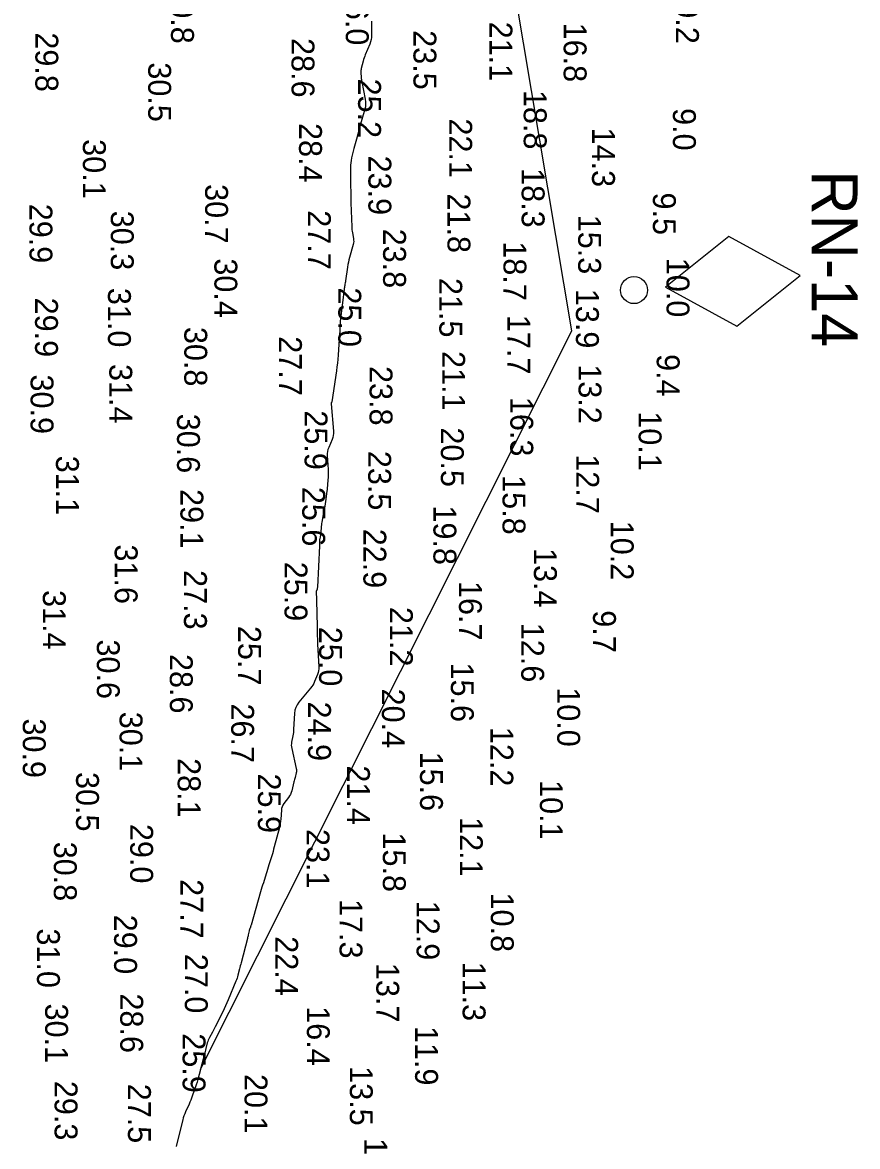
# Model space of a CAD drawing. Extents: x 1178573 to 1187098, y 693282 to 751751.
# Drawn here: x 1180607 to 1181063, y 712737 to 713352 of the extents above; entities that cross this region are included whole.
import ezdxf

# ---------------------------------------------------------------- set-up
doc = ezdxf.new("R2010")
doc.units = 0
for name, color, linetype in [('G-ANNO-PATT', 7, 'Continuous'), ('V-CHAN-NAID', 7, 'Continuous'), ('V-HYDS-MAJR', 7, 'Continuous'), ('V-HYDS-SOUN', 7, 'Continuous'), ('V-HYDS-SOUN-EXSS', 7, 'Continuous')]:
    doc.layers.add(name, color=color, linetype=linetype)

msp = doc.modelspace()

# ---------------------------------------------------------------- linework, layer by layer
at = {"layer": 'G-ANNO-PATT'}
msp.add_line((1180704.33, 712779.5), (1180907.13, 713183.08), dxfattribs=at)
for points in [[(1180907.13, 713183.08), (1180828.13, 713654.46), (1180762.78, 713744.18)], [(1180797.74, 713352.4), (1180797.72, 713351.58), (1180797.71, 713350.75), (1180797.7, 713344.77), (1180797.64, 713343.51), (1180797.46, 713342.28), (1180797.15, 713341.07), (1180796.73, 713339.88), (1180794.29, 713333.99), (1180793.96, 713333.15), (1180793.66, 713332.31), (1180793.39, 713331.45), (1180793.14, 713330.58), (1180792.08, 713326.51), (1180791.95, 713325.92), (1180791.88, 713325.32), (1180791.85, 713324.72), (1180791.87, 713324.12), (1180792.07, 713321.69), (1180792.12, 713321.09), (1180792.2, 713320.48), (1180792.29, 713319.88), (1180792.4, 713319.29), (1180794.25, 713309.72), (1180794.44, 713308.33), (1180794.47, 713306.94), (1180794.33, 713305.56), (1180794.02, 713304.19), (1180792.45, 713298.65), (1180792.08, 713297.31), (1180791.7, 713295.98), (1180791.33, 713294.64), (1180790.95, 713293.31), (1180789.43, 713287.85), (1180789.08, 713286.57), (1180788.74, 713285.29), (1180788.41, 713284.01), (1180788.09, 713282.72), (1180786.83, 713277.58), (1180786.55, 713276.29), (1180786.36, 713274.99), (1180786.25, 713273.68), (1180786.22, 713272.36), (1180786.29, 713261.84), (1180786.31, 713259.64), (1180786.35, 713257.45), (1180786.4, 713255.25), (1180786.46, 713253.06), (1180786.88, 713239.95), (1180786.92, 713239.13), (1180786.99, 713238.32), (1180787.09, 713237.52), (1180787.23, 713236.72), (1180787.83, 713233.51), (1180787.93, 713232.72), (1180787.95, 713231.92), (1180787.87, 713231.13), (1180787.69, 713230.34), (1180785.73, 713223.26), (1180785.39, 713221.95), (1180785.1, 713220.64), (1180784.84, 713219.31), (1180784.63, 713217.98), (1180783.56, 713210.46), (1180783.52, 713210.21), (1180783.48, 713209.96), (1180783.43, 713209.72), (1180783.38, 713209.47), (1180783.17, 713208.48), (1180783.12, 713208.25), (1180783.08, 713208.01), (1180783.04, 713207.77), (1180783, 713207.54), (1180782.87, 713206.59), (1180782.84, 713206.35), (1180782.8, 713206.11), (1180782.77, 713205.87), (1180782.74, 713205.63), (1180780.64, 713188.46), (1180780.58, 713187.89), (1180780.53, 713187.32), (1180780.49, 713186.75), (1180780.46, 713186.18), (1180780.38, 713183.89), (1180780.36, 713183.32), (1180780.33, 713182.75), (1180780.3, 713182.18), (1180780.26, 713181.6), (1180779.46, 713169.8), (1180779.29, 713167.65), (1180779.07, 713165.5), (1180778.82, 713163.35), (1180778.52, 713161.21), (1180775.98, 713144.23), (1180775.97, 713144.16), (1180775.95, 713144.1), (1180775.92, 713144.03), (1180775.88, 713143.97), (1180775.7, 713143.67), (1180775.68, 713143.63), (1180775.67, 713143.59), (1180775.67, 713143.55), (1180775.67, 713143.51), (1180775.7, 713143.34), (1180775.71, 713143.3), (1180775.71, 713143.26), (1180775.72, 713143.21), (1180775.72, 713143.17), (1180776.9, 713128.24), (1180776.93, 713127.08), (1180776.81, 713125.94), (1180776.56, 713124.83), (1180776.16, 713123.74), (1180774.31, 713119.42), (1180773.91, 713118.32), (1180773.65, 713117.21), (1180773.52, 713116.07), (1180773.52, 713114.91), (1180773.97, 713107.29), (1180774.01, 713106.3), (1180774.02, 713105.31), (1180774, 713104.32), (1180773.95, 713103.33), (1180773.68, 713099.37), (1180773.6, 713098.38), (1180773.51, 713097.4), (1180773.4, 713096.41), (1180773.27, 713095.43), (1180772.51, 713089.87), (1180772.33, 713088.62), (1180772.14, 713087.37), (1180771.93, 713086.12), (1180771.71, 713084.88), (1180770.53, 713078.47), (1180770.4, 713077.73), (1180770.29, 713076.99), (1180770.2, 713076.24), (1180770.13, 713075.49), (1180769.8, 713071.54), (1180769.77, 713071.26), (1180769.74, 713070.99), (1180769.69, 713070.72), (1180769.64, 713070.45), (1180769.41, 713069.38), (1180769.36, 713069.12), (1180769.33, 713068.85), (1180769.31, 713068.57), (1180769.3, 713068.3), (1180769.31, 713066.94), (1180769.31, 713066.62), (1180769.31, 713066.3), (1180769.3, 713065.98), (1180769.29, 713065.67), (1180768.13, 713043.08), (1180768.1, 713042.76), (1180768.06, 713042.45), (1180767.99, 713042.14), (1180767.91, 713041.83), (1180767.54, 713040.61), (1180767.47, 713040.3), (1180767.42, 713039.99), (1180767.4, 713039.68), (1180767.42, 713039.36), (1180767.58, 713037.43), (1180767.62, 713037.01), (1180767.65, 713036.58), (1180767.66, 713036.15), (1180767.67, 713035.72), (1180767.91, 713021.58), (1180767.97, 713019.15), (1180768.04, 713016.72), (1180768.14, 713014.28), (1180768.25, 713011.85), (1180768.91, 712999.4), (1180768.91, 712998.35), (1180768.79, 712997.31), (1180768.56, 712996.3), (1180768.2, 712995.31), (1180766.56, 712991.39), (1180766.11, 712990.43), (1180765.6, 712989.51), (1180765.02, 712988.63), (1180764.37, 712987.8), (1180758, 712980.19), (1180757.01, 712978.79), (1180756.27, 712977.3), (1180755.8, 712975.71), (1180755.58, 712974.01), (1180755.15, 712965.31), (1180755.09, 712964.43), (1180754.99, 712963.55), (1180754.87, 712962.68), (1180754.71, 712961.81), (1180754.02, 712958.33), (1180753.89, 712957.47), (1180753.86, 712956.6), (1180753.92, 712955.74), (1180754.07, 712954.87), (1180756.56, 712943.93), (1180756.67, 712943.31), (1180756.69, 712942.7), (1180756.65, 712942.09), (1180756.53, 712941.48), (1180755.89, 712939.03), (1180755.73, 712938.42), (1180755.57, 712937.81), (1180755.42, 712937.2), (1180755.27, 712936.58), (1180754.08, 712931.7), (1180753.79, 712930.72), (1180753.4, 712929.78), (1180752.92, 712928.9), (1180752.34, 712928.05), (1180749.84, 712924.77), (1180749.28, 712923.93), (1180748.87, 712923.03), (1180748.59, 712922.08), (1180748.45, 712921.07), (1180748.13, 712916.19), (1180748.03, 712915.04), (1180747.87, 712913.9), (1180747.65, 712912.76), (1180747.38, 712911.64), (1180744.56, 712901.04), (1180744.22, 712899.8), (1180743.87, 712898.56), (1180743.51, 712897.33), (1180743.14, 712896.1), (1180741.64, 712891.16), (1180741.26, 712889.94), (1180740.88, 712888.72), (1180740.5, 712887.5), (1180740.12, 712886.28), (1180738.59, 712881.4), (1180738.21, 712880.18), (1180737.83, 712878.96), (1180737.47, 712877.74), (1180737.11, 712876.51), (1180731.89, 712858.29), (1180731.81, 712858.03), (1180731.73, 712857.77), (1180731.63, 712857.52), (1180731.53, 712857.27), (1180731.12, 712856.26), (1180731.02, 712856.01), (1180730.94, 712855.76), (1180730.86, 712855.49), (1180730.8, 712855.23), (1180730.34, 712852.93), (1180730.24, 712852.45), (1180730.13, 712851.98), (1180730.02, 712851.51), (1180729.9, 712851.05), (1180726.44, 712837.74), (1180726.21, 712836.89), (1180726, 712836.03), (1180725.78, 712835.18), (1180725.56, 712834.33), (1180724.7, 712830.92), (1180724.47, 712830.07), (1180724.21, 712829.24), (1180723.92, 712828.41), (1180723.59, 712827.59), (1180719.38, 712817.46), (1180718.67, 712815.8), (1180717.94, 712814.15), (1180717.18, 712812.51), (1180716.4, 712810.88), (1180712.35, 712802.64), (1180711.98, 712801.9), (1180711.6, 712801.17), (1180711.21, 712800.44), (1180710.8, 712799.72), (1180709.13, 712796.8), (1180708.76, 712796.1), (1180708.45, 712795.38), (1180708.18, 712794.64), (1180707.97, 712793.88), (1180707.23, 712790.8), (1180707.05, 712790.03), (1180706.86, 712789.27), (1180706.66, 712788.5), (1180706.47, 712787.73), (1180704.33, 712779.5)]]:
    msp.add_lwpolyline(points, dxfattribs=at)
at = {"layer": 'V-CHAN-NAID'}
msp.add_lwpolyline([(1180958.3, 713206.9), (1180997.3, 713185.6), (1181031.95, 713213.41), (1180992.96, 713234.7)], close=True, dxfattribs=at)
msp.add_circle((1180941.12, 713205.38), 7.39, dxfattribs=at)
at = {"layer": 'V-HYDS-MAJR'}
msp.add_lwpolyline([(1180797.74, 713352.4), (1180797.72, 713351.58), (1180797.71, 713350.75), (1180797.7, 713344.77), (1180797.64, 713343.51), (1180797.46, 713342.28), (1180797.15, 713341.07), (1180796.73, 713339.88), (1180794.29, 713333.99), (1180793.96, 713333.15), (1180793.66, 713332.31), (1180793.39, 713331.45), (1180793.14, 713330.58), (1180792.08, 713326.51), (1180791.95, 713325.92), (1180791.88, 713325.32), (1180791.85, 713324.72), (1180791.87, 713324.12), (1180792.07, 713321.69), (1180792.12, 713321.09), (1180792.2, 713320.48), (1180792.29, 713319.88), (1180792.4, 713319.29), (1180794.25, 713309.72), (1180794.44, 713308.33), (1180794.47, 713306.94), (1180794.33, 713305.56), (1180794.02, 713304.19), (1180792.45, 713298.65), (1180792.08, 713297.31), (1180791.7, 713295.98), (1180791.33, 713294.64), (1180790.95, 713293.31), (1180789.43, 713287.85), (1180789.08, 713286.57), (1180788.74, 713285.29), (1180788.41, 713284.01), (1180788.09, 713282.72), (1180786.83, 713277.58), (1180786.55, 713276.29), (1180786.36, 713274.99), (1180786.25, 713273.68), (1180786.22, 713272.36), (1180786.29, 713261.84), (1180786.31, 713259.64), (1180786.35, 713257.45), (1180786.4, 713255.25), (1180786.46, 713253.06), (1180786.88, 713239.95), (1180786.92, 713239.13), (1180786.99, 713238.32), (1180787.09, 713237.52), (1180787.23, 713236.72), (1180787.83, 713233.51), (1180787.93, 713232.72), (1180787.95, 713231.92), (1180787.87, 713231.13), (1180787.69, 713230.34), (1180785.73, 713223.26), (1180785.39, 713221.95), (1180785.1, 713220.64), (1180784.84, 713219.31), (1180784.63, 713217.98), (1180783.56, 713210.46), (1180783.52, 713210.21), (1180783.48, 713209.96), (1180783.43, 713209.72), (1180783.38, 713209.47), (1180783.17, 713208.48), (1180783.12, 713208.25), (1180783.08, 713208.01), (1180783.04, 713207.77), (1180783, 713207.54), (1180782.87, 713206.59), (1180782.84, 713206.35), (1180782.8, 713206.11), (1180782.77, 713205.87), (1180782.74, 713205.63), (1180780.64, 713188.46), (1180780.58, 713187.89), (1180780.53, 713187.32), (1180780.49, 713186.75), (1180780.46, 713186.18), (1180780.38, 713183.89), (1180780.36, 713183.32), (1180780.33, 713182.75), (1180780.3, 713182.18), (1180780.26, 713181.6), (1180779.46, 713169.8), (1180779.29, 713167.65), (1180779.07, 713165.5), (1180778.82, 713163.35), (1180778.52, 713161.21), (1180775.98, 713144.23), (1180775.97, 713144.16), (1180775.95, 713144.1), (1180775.92, 713144.03), (1180775.88, 713143.97), (1180775.7, 713143.67), (1180775.68, 713143.63), (1180775.67, 713143.59), (1180775.67, 713143.55), (1180775.67, 713143.51), (1180775.7, 713143.34), (1180775.71, 713143.3), (1180775.71, 713143.26), (1180775.72, 713143.21), (1180775.72, 713143.17), (1180776.9, 713128.24), (1180776.93, 713127.08), (1180776.81, 713125.94), (1180776.56, 713124.83), (1180776.16, 713123.74), (1180774.31, 713119.42), (1180773.91, 713118.32), (1180773.65, 713117.21), (1180773.52, 713116.07), (1180773.52, 713114.91), (1180773.97, 713107.29), (1180774.01, 713106.3), (1180774.02, 713105.31), (1180774, 713104.32), (1180773.95, 713103.33), (1180773.68, 713099.37), (1180773.6, 713098.38), (1180773.51, 713097.4), (1180773.4, 713096.41), (1180773.27, 713095.43), (1180772.51, 713089.87), (1180772.33, 713088.62), (1180772.14, 713087.37), (1180771.93, 713086.12), (1180771.71, 713084.88), (1180770.53, 713078.47), (1180770.4, 713077.73), (1180770.29, 713076.99), (1180770.2, 713076.24), (1180770.13, 713075.49), (1180769.8, 713071.54), (1180769.77, 713071.26), (1180769.74, 713070.99), (1180769.69, 713070.72), (1180769.64, 713070.45), (1180769.41, 713069.38), (1180769.36, 713069.12), (1180769.33, 713068.85), (1180769.31, 713068.57), (1180769.3, 713068.3), (1180769.31, 713066.94), (1180769.31, 713066.62), (1180769.31, 713066.3), (1180769.3, 713065.98), (1180769.29, 713065.67), (1180768.13, 713043.08), (1180768.1, 713042.76), (1180768.06, 713042.45), (1180767.99, 713042.14), (1180767.91, 713041.83), (1180767.54, 713040.61), (1180767.47, 713040.3), (1180767.42, 713039.99), (1180767.4, 713039.68), (1180767.42, 713039.36), (1180767.58, 713037.43), (1180767.62, 713037.01), (1180767.65, 713036.58), (1180767.66, 713036.15), (1180767.67, 713035.72), (1180767.91, 713021.58), (1180767.97, 713019.15), (1180768.04, 713016.72), (1180768.14, 713014.28), (1180768.25, 713011.85), (1180768.91, 712999.4), (1180768.91, 712998.35), (1180768.79, 712997.31), (1180768.56, 712996.3), (1180768.2, 712995.31), (1180766.56, 712991.39), (1180766.11, 712990.43), (1180765.6, 712989.51), (1180765.02, 712988.63), (1180764.37, 712987.8), (1180758, 712980.19), (1180757.01, 712978.79), (1180756.27, 712977.3), (1180755.8, 712975.71), (1180755.58, 712974.01), (1180755.15, 712965.31), (1180755.09, 712964.43), (1180754.99, 712963.55), (1180754.87, 712962.68), (1180754.71, 712961.81), (1180754.02, 712958.33), (1180753.89, 712957.47), (1180753.86, 712956.6), (1180753.92, 712955.74), (1180754.07, 712954.87), (1180756.56, 712943.93), (1180756.67, 712943.31), (1180756.69, 712942.7), (1180756.65, 712942.09), (1180756.53, 712941.48), (1180755.89, 712939.03), (1180755.73, 712938.42), (1180755.57, 712937.81), (1180755.42, 712937.2), (1180755.27, 712936.58), (1180754.08, 712931.7), (1180753.79, 712930.72), (1180753.4, 712929.78), (1180752.92, 712928.9), (1180752.34, 712928.05), (1180749.84, 712924.77), (1180749.28, 712923.93), (1180748.87, 712923.03), (1180748.59, 712922.08), (1180748.45, 712921.07), (1180748.13, 712916.19), (1180748.03, 712915.04), (1180747.87, 712913.9), (1180747.65, 712912.76), (1180747.38, 712911.64), (1180744.56, 712901.04), (1180744.22, 712899.8), (1180743.87, 712898.56), (1180743.51, 712897.33), (1180743.14, 712896.1), (1180741.64, 712891.16), (1180741.26, 712889.94), (1180740.88, 712888.72), (1180740.5, 712887.5), (1180740.12, 712886.28), (1180738.59, 712881.4), (1180738.21, 712880.18), (1180737.83, 712878.96), (1180737.47, 712877.74), (1180737.11, 712876.51), (1180731.89, 712858.29), (1180731.81, 712858.03), (1180731.73, 712857.77), (1180731.63, 712857.52), (1180731.53, 712857.27), (1180731.12, 712856.26), (1180731.02, 712856.01), (1180730.94, 712855.76), (1180730.86, 712855.49), (1180730.8, 712855.23), (1180730.34, 712852.93), (1180730.24, 712852.45), (1180730.13, 712851.98), (1180730.02, 712851.51), (1180729.9, 712851.05), (1180726.44, 712837.74), (1180726.21, 712836.89), (1180726, 712836.03), (1180725.78, 712835.18), (1180725.56, 712834.33), (1180724.7, 712830.92), (1180724.47, 712830.07), (1180724.21, 712829.24), (1180723.92, 712828.41), (1180723.59, 712827.59), (1180719.38, 712817.46), (1180718.67, 712815.8), (1180717.94, 712814.15), (1180717.18, 712812.51), (1180716.4, 712810.88), (1180712.35, 712802.64), (1180711.98, 712801.9), (1180711.6, 712801.17), (1180711.21, 712800.44), (1180710.8, 712799.72), (1180709.13, 712796.8), (1180708.76, 712796.1), (1180708.45, 712795.38), (1180708.18, 712794.64), (1180707.97, 712793.88), (1180707.23, 712790.8), (1180707.05, 712790.03), (1180706.86, 712789.27), (1180706.66, 712788.5), (1180706.47, 712787.73), (1180703.61, 712776.72), (1180703.22, 712775.29), (1180702.81, 712773.86), (1180702.36, 712772.44), (1180701.89, 712771.03), (1180699.73, 712764.79), (1180699.33, 712763.69), (1180698.91, 712762.61), (1180698.47, 712761.53), (1180697.99, 712760.46), (1180696.06, 712756.2), (1180695.6, 712755.13), (1180695.19, 712754.04), (1180694.83, 712752.93), (1180694.53, 712751.8), (1180690.96, 712737.48), (1180690.94, 712737.41), (1180690.92, 712737.34), (1180690.9, 712737.28)], dxfattribs=at)

# ---------------------------------------------------------------- texts
at = {"layer": 'V-CHAN-NAID'}
msp.add_text('RN-14', height=25, rotation=270, dxfattribs=at).set_placement((1181038.26, 713270.77))
at = {"layer": 'V-HYDS-SOUN'}
for s, p in [('30.8 ', (1180688.16, 713372.57)), ('26.0 ', (1180783.66, 713371.69)), ('9.2', (1180964.08, 713363.19)), ('21.1 ', (1180862.15, 713352.09)), ('16.8 ', (1180902.7, 713351.57)), ('29.8 ', (1180614.02, 713346.25)), ('28.6 ', (1180754, 713343.14)), ('23.5 ', (1180820.61, 713347.45)), ('30.5 ', (1180675.69, 713329.86)), ('25.2 ', (1180790.37, 713320.99)), ('18.8 ', (1180880.88, 713314.79)), ('9.0', (1180962.41, 713304.86)), ('22.1 ', (1180840.17, 713299.2)), ('28.4 ', (1180758.1, 713296.69)), ('14.3 ', (1180918.2, 713294.22)), ('30.1 ', (1180640, 713287.88)), ('23.9 ', (1180796, 713278.9)), ('18.3 ', (1180879.75, 713272.04)), ('30.7 ', (1180706.79, 713263.31)), ('21.8 ', (1180839.21, 713258.2)), ('9.5', (1180951.48, 713258.71)), ('29.9 ', (1180610.8, 713252.59)), ('30.3 ', (1180655.25, 713248.75)), ('27.7 ', (1180762.95, 713249.01)), ('15.3 ', (1180910.63, 713246.58)), ('23.8 ', (1180804.04, 713238.94)), ('18.7 ', (1180869.81, 713232.05)), ('30.4 ', (1180711.84, 713222.74)), ('31.0 ', (1180653.7, 713206.6)), ('25.0 ', (1180779.56, 713206.86)), ('21.5 ', (1180834.75, 713212.02)), ('29.9 ', (1180613.85, 713201.27)), ('13.9 ', (1180909.42, 713206.06)), ('17.7 ', (1180871.94, 713191.83)), ('30.8 ', (1180695.41, 713185.26)), ('27.7 ', (1180747.14, 713180.15)), ('21.1 ', (1180836.33, 713172.07)), ('9.4', (1180953.55, 713170.41)), ('31.4 ', (1180654.43, 713165)), ('23.8 ', (1180796.66, 713163.87)), ('13.2 ', (1180910.85, 713164.85)), ('30.9 ', (1180611.42, 713159.25)), ('16.3 ', (1180873.55, 713147.01)), ('25.9 ', (1180761.13, 713139.66)), ('10.1 ', (1180943.68, 713139.16)), ('30.6 ', (1180691.43, 713137.82)), ('20.5 ', (1180835.6, 713130.32)), ('31.1 ', (1180625.3, 713114.88)), ('23.5 ', (1180795.9, 713117.53)), ('12.7 ', (1180909.58, 713115.64)), ('15.8 ', (1180869.3, 713104.23)), ('29.1 ', (1180693.28, 713096.64)), ('25.6 ', (1180759.87, 713097.86)), ('19.8 ', (1180831.53, 713087.69)), ('10.2 ', (1180928.43, 713079.32)), ('22.9 ', (1180793.25, 713074.96)), ('31.6 ', (1180657.38, 713066.37)), ('13.4 ', (1180886.45, 713064.41)), ('25.9 ', (1180750.17, 713056.92)), ('27.3 ', (1180695.24, 713052.36)), ('31.4 ', (1180618.11, 713041.44)), ('16.7 ', (1180845.5, 713046.42)), ('21.2 ', (1180807.76, 713032.21)), ('9.7', (1180918.74, 713030.38)), ('12.6 ', (1180879.52, 713023.55)), ('25.7 ', (1180724.83, 713021.85)), ('25.0 ', (1180769.06, 713021.36)), ('30.6 ', (1180647.63, 713014.43)), ('28.6 ', (1180687.5, 713006.49)), ('15.6 ', (1180841.07, 713001.83)), ('20.4 ', (1180803.37, 712987.57)), ('10.0 ', (1180899.18, 712988.32)), ('26.7 ', (1180721.03, 712979.46)), ('24.9 ', (1180763.03, 712980.51)), ('30.1 ', (1180660.05, 712974.92)), ('30.9 ', (1180607.16, 712971.26)), ('12.2 ', (1180862.65, 712966.66)), ('28.1 ', (1180691.81, 712949.59)), ('15.6 ', (1180824.21, 712953.14)), ('30.5 ', (1180636.26, 712942)), ('21.4 ', (1180784.31, 712945.61)), ('25.9 ', (1180735.64, 712941.17)), ('10.1 ', (1180889.71, 712937.59)), ('29.0 ', (1180665.84, 712913.62)), ('12.1 ', (1180845.97, 712917.34)), ('23.1 ', (1180762.21, 712910.85)), ('15.8 ', (1180803.91, 712908.95)), ('30.8 ', (1180624.12, 712903.9)), ('27.7 ', (1180693.24, 712883.43)), ('10.8 ', (1180862.9, 712876.11)), ('17.3 ', (1180780.24, 712872.57)), ('12.9 ', (1180822.35, 712871.62)), ('29.0 ', (1180657.05, 712864.01)), ('31.0 ', (1180614.92, 712856.5)), ('22.4 ', (1180745.07, 712852.24)), ('27.0 ', (1180695.7, 712842.62)), ('11.3 ', (1180847.5, 712838.38)), ('13.7 ', (1180800.32, 712837.66)), ('28.6 ', (1180660.43, 712820.96)), ('30.1 ', (1180619.37, 712815.44)), ('16.4 ', (1180762.4, 712813.98)), ('11.9 ', (1180821.53, 712803.21)), ('25.9 ', (1180694.49, 712799.18)), ('20.1 ', (1180728.32, 712776.92)), ('13.5 ', (1180785.87, 712781.21)), ('29.3 ', (1180624.54, 712773.19)), ('27.5 ', (1180664.64, 712771.63)), ('12.2 ', (1180793.75, 712741.89))]:
    msp.add_text(s, height=12.5, rotation=270, dxfattribs=at).set_placement(p)
at = {"layer": 'V-HYDS-SOUN-EXSS'}
msp.add_text('10.0 ', height=12.5, rotation=270, dxfattribs=at).set_placement((1180958.92, 713223.04))

doc.saveas('drawing.dxf')
